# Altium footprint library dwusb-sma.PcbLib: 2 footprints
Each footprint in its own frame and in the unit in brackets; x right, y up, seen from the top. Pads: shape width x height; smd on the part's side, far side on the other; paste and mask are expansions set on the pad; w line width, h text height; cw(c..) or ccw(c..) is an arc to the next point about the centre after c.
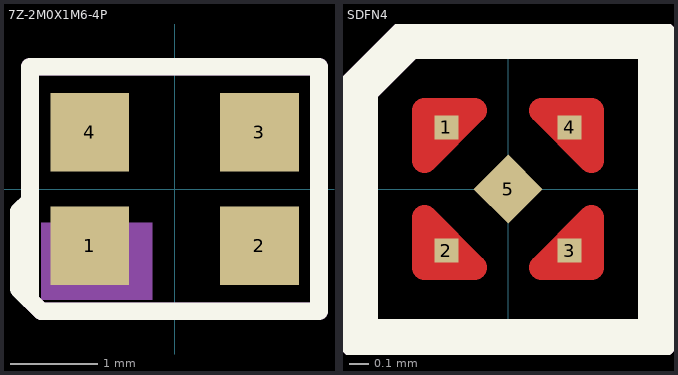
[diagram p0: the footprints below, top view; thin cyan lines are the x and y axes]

## 7Z-2M0X1M6-4P [mm]
pads (4):
  rect 0.9x0.9 smd: 1(-0.97,-0.65) 2(0.97,-0.65) 3(0.97,0.65) 4(-0.97,0.65)
Top Overlay:
  lines w0.203: -1.651,-1.27 -1.651,1.397 1.651,1.397 1.651,-1.397 -1.524,-1.397 -1.778,-1.143 -1.778,-0.381 -1.778,-0.254 -1.651,-0.127
  text ".Designator" at -2.032,-2.413 h0.89
Mechanical 2:
  rectangle: -1.524,-1.27 -0.254,-0.381
  lines w0.203: -1.651,-1.27 -1.651,1.397 1.651,1.397 1.651,-1.397 -1.524,-1.397 -1.651,-1.27
3D body: height 0.75, standoff 0, extent -1.275,-1.05 1.25,1.05

## SDFN4 [mm]
height 0.38
pads (5):
  rect 0.12x0.12 smd paste+0 mask-0.051: 1(-0.312,0.312) 2(-0.312,-0.312) 3(0.312,-0.312) 4(0.312,0.312)
  rect 0.25x0.25 smd rot 135 paste+0 mask+0.051: 5(0,0)
Top Layer:
  region: 0.425,0.145 0.425,0.4 0.17,0.4
  region: 0.425,-0.4 0.425,-0.145 0.17,-0.4
  region: -0.425,-0.4 -0.425,-0.145 -0.17,-0.4
  region: -0.425,0.145 -0.425,0.4 -0.17,0.4
  lines w0.127: -0.425,-0.4 -0.425,-0.145 -0.17,-0.4 -0.425,-0.4 ; -0.425,0.145 -0.17,0.4 -0.425,0.4 -0.425,0.145 ; 0.17,-0.4 0.425,-0.145 0.425,-0.4 0.17,-0.4 ; 0.17,0.4 0.425,0.145 0.425,0.4 0.17,0.4
Top Overlay:
  lines w0.203: -0.762,-0.762 0.762,-0.762 0.762,0.762 -0.508,0.762 -0.762,0.508 -0.762,-0.762
  text ".Designator" at -0.925,1.05 h0.89
Mechanical 2:
  lines w0.203: -0.762,-0.762 0.762,-0.762 0.762,0.762 -0.508,0.762 -0.762,0.508 -0.762,-0.762
3D body: height 0.4, standoff 0.04, extent -0.4,-0.4 0.4,0.4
